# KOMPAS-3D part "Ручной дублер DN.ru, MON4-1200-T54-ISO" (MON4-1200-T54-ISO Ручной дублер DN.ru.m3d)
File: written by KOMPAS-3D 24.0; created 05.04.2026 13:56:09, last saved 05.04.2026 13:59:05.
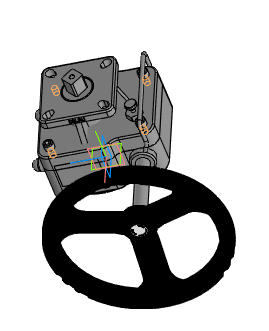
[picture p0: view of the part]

Document properties: Автор: R2D2; Полное имя файла: E:\Работа\Зайцев\Аксессуары для пневмоприводов\Ручной дублер DN.ru\MON4-1200-T54-ISO Ручной дублер DN.ru\исходные материалы\MON4-1200-T54-ISO Ручной дублер DN.ru.m3d

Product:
- Component [detail]: Деталь1  | qty 1  | pos. 1  | Масса: 35.407781; additional columns: Типовые; source file: 3.m3d
- Component [detail]: Деталь1  | qty 1  | pos. 1  | Масса: 35.407781; Автор: R2D2; additional columns: Типовые; source file: 2.m3d
- Component [detail]: Деталь1  | qty 1  | pos. 1  | Масса: 35.407781; Автор: R2D2; additional columns: Типовые; source file: 1.m3d
- Component [detail]: Деталь 2  | qty 1  | pos. 2  | Масса: 6.906855; Автор: R2D2; additional columns: Типовые; source file: Деталь 2 Деталь 2.m3d
- Component [standard]: Hexagon socket head cap screw ISO 4762 - М12 x 20  | qty 4  | Материал: Не определено (density 0 kg/m3); Масса: 0.0321; Раздел спецификации: Стандартные изделия; Рассекать на разрезах: no
- Part/product: Ручной дублер DN.ru  | designation MON4-1200-T54-ISO
    Масса: 13.7
    Раздел спецификации: Прочие изделия
    Примечание: D290-00339

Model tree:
1. Эскиз:1  (with: Грань.Операция без истории:1, Ребро.Операция без истории:1)
2. Элемент выдавливания:1
     Расстояние 2 = 32
3. Эскиз:2  (with: Грань.Операция без истории:1, Ребро.Операция без истории:1)
4. Элемент выдавливания:2
     Расстояние 2 = 16
5. Эскиз:3  (with: Грань.Операция без истории:1, Ребро.Операция без истории:1)
6. Элемент выдавливания:3  (with: Грань.Элемент выдавливания:1, Грань.Операция без истории:1)  (labels: Грань.Твердое тело1)
     Расстояние 2 = 19; Расстояние = 10; Расстояние = -195; Расстояние = -280

Referenced files in E:\Работа\Зайцев\Аксессуары для пневмоприводов\Ручной дублер DN.ru\MON4-1200-T54-ISO Ручной дублер DN.ru\исходные материалы\: 3.m3d, 2.m3d, 1.m3d, Деталь 2 Деталь 2.m3d
Referenced files in C:\Program Files\ASCON\KOMPAS-3D v24\Libs\PolynomLib\DATA\vault\Methods\Kompas\3D\: PLib_Screw_DIN_7984_1500.m3d
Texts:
  BOSimple***PART:d0712955-55fa-f496-1eba-993b7d03c8f4***SHORTLOC:A259_235BDFABBEFC4171[1,75;20;12;-;Undefined]
  MON4-1200-T54-ISO
  Деталь1 Деталь1
  Деталь 2 Деталь 2
  Hexagon socket head cap screw ISO 4762 - М12 x 20 (1)
  Hexagon socket head cap screw ISO 4762 - М12 x 20 (2)
  Hexagon socket head cap screw ISO 4762 - М12 x 20 (3)
  Hexagon socket head cap screw ISO 4762 - М12 x 20 (4)
  Ось Y.Начало координат
  Плоскость ZX.Начало координат
  Плоскость ZY.Начало координат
